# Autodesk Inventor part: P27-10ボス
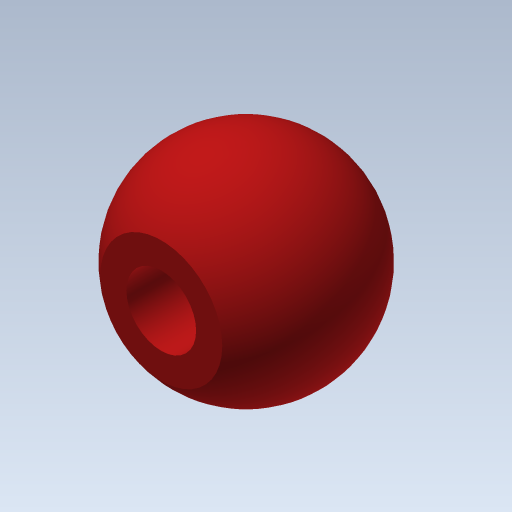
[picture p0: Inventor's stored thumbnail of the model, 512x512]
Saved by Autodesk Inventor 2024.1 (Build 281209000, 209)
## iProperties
Created: 2008-07
Part Number: P27-10ボス
Document SubType Name: Modeling
Designer: y-shimohigashi
Density: 1 g/cm^3
Stock Number: P24-10ボス
Material: 一般
Appearance: 淡い赤-オレンジ
Author: y-shimohigashi
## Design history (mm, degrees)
revolve "回転1" stored, may be unused: angle "d4" = 90 deg
node "ソリッド1"
node "ソリッド ボディ"
node "サーフェス ボディ"
sketch "スケッチ1"
  geometry: L1 (0, 12)-(0, 3.253); L2 (0, 3.253)-(4, 3.253); L3 (4, 3.253)-(4, -9.747); L4 (4, -9.747)-(7, -9.747); A1 r 12 centre (0, 0) between (7, -9.747) and (0, 12); 1 further point
  constraints: 8 end point, 2 parallel, 2 point on circle, 1 centre point, 1 coincident, 1 perpendicular, 1 point on line, 1 vertical
  dimensions: "d0" = 4 distance of L1.end L2.end; "d1" = 3 distance of L3.end L4.end; "d2" = 13 distance of L2.end L3.end; "d3" = 12 radius of A1
